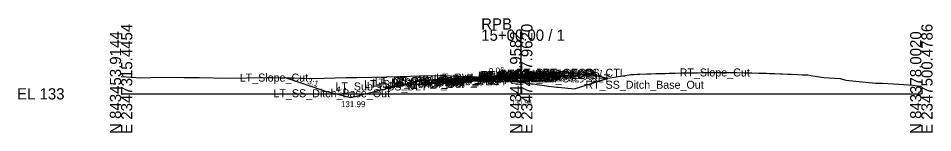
# Model space of a CAD drawing. Extents: x -76 to 2347760, y -10 to 844216.
# Drawn here: x -25.7 to 202.8, y -9.7 to 18.9 of the extents above; entities that cross this region are included whole.
import ezdxf

# ---------------------------------------------------------------- set-up
doc = ezdxf.new("R2010")
doc.units = 0
for name, color, linetype in [('Default', 7, 'Continuous'), ('Exist Cross Section Cell', 7, 'Continuous'), ('Exist XS Center Line Elevation Label', 7, 'Continuous'), ('Exist XS Ground Line', 7, 'Continuous'), ('Prop CMT Pvmt Course 1', 7, 'Continuous'), ('Prop CMT Pvmt Course 2', 7, 'Continuous'), ('Prop CMT Pvmt Course 3', 7, 'Continuous'), ('Prop CMT Pvmt Surface', 7, 'Continuous'), ('Prop CMT Pvmt Surface Shoulder', 7, 'Continuous'), ('Prop CMT Shld Paved Course 1', 7, 'Continuous'), ('Prop CMT Shld Paved Course 2', 7, 'Continuous'), ('Prop CMT Shld Paved Course 3', 7, 'Continuous'), ('Prop CMT Slope Grass', 7, 'Continuous'), ('Prop CMT Subgrade Earthwork', 7, 'Continuous'), ('Prop XS Ditch Standard Text', 7, 'Continuous'), ('Prop XS Earthwork Shape', 7, 'Continuous'), ('Prop XS SE Text', 7, 'Continuous'), ('Prop XS Side Slope Text', 7, 'Continuous'), ('Scratch_Level_0', 7, 'Continuous')]:
    doc.layers.add(name, color=color, linetype=linetype)

msp = doc.modelspace()

# ---------------------------------------------------------------- linework, layer by layer
at = {"layer": 'Exist Cross Section Cell'}
for p, q in [((100, 0), (100, 16.05)), ((0, 0), (100, 0)), ((100, 0), (200, 0))]:
    msp.add_line(p, q, dxfattribs=at)
at = {"layer": 'Exist XS Ground Line'}
msp.add_lwpolyline([(0, 4.33), (1.29, 4.27), (4.85, 4.03), (9.98, 4.14), (15.66, 4.12), (19.62, 4.12), (26.47, 3.9), (36.32, 4.12), (37.28, 4.11), (37.95, 4.11), (48.09, 3.87), (56.28, 4.11), (58.9, 4.11), (62.67, 4.2), (69.71, 4.3), (74.6, 4.51), (80.52, 4.57), (89.02, 4.24), (91.33, 4.06), (98.32, 3.17), (100, 2.93), (106.94, 1.94), (108.89, 1.64), (109.26, 1.63), (113.33, 1.28), (117.25, 2.5), (121.67, 3.89), (123.84, 4.22), (127.44, 4.85), (128.15, 4.83), (128.91, 4.89), (129.63, 4.92), (131.41, 4.98), (132.36, 5), (133.64, 5.04), (135.08, 5.08), (136.01, 5.11), (136.99, 5.14), (137.89, 5.15), (138.47, 5.17), (140.43, 5.21), (142.3, 5.24), (143.15, 5.26), (144.22, 5.28), (145.88, 5.31), (146.86, 5.33), (148.35, 5.35), (148.79, 5.34), (150.08, 5.34), (151.22, 5.33), (153.39, 5.31), (153.92, 5.3), (155.71, 5.27), (156.65, 5.26), (157.62, 5.24), (159.37, 5.2), (160, 5.19), (161.34, 5.15), (162.06, 5.12), (163.37, 5.07), (164.76, 5.02), (165.28, 5), (166.65, 4.94), (167.45, 4.91), (169.1, 4.83), (170.25, 4.76), (170.94, 4.71), (171.64, 4.71), (172.88, 4.51), (175.65, 4.07), (179.69, 3.85), (181.14, 3.4), (188.61, 2.7), (190.3, 2.68), (194.41, 2.4), (197.96, 2.17), (199.45, 1.96), (200, 1.88)], dxfattribs=at)
at = {"layer": 'Prop CMT Pvmt Course 1'}
for p, q in [((100, 4.79), (88, 4.07)), ((100, 4.79), (104, 5.03)), ((100, 4.54), (100, 4.79)), ((100, 4.54), (100, 4.79)), ((104, 4.78), (100, 4.54)), ((100, 4.54), (100, 4.67)), ((100, 4.67), (100, 4.67)), ((100, 4.67), (100, 4.54)), ((100, 4.54), (100, 4.67)), ((100, 4.67), (100, 4.67)), ((100, 4.67), (100, 4.54)), ((104, 5.03), (104, 4.78)), ((88, 3.82), (100, 4.54)), ((88, 4.07), (88, 3.82)), ((100, 4.54), (100, 4.54)), ((100, 4.54), (100, 4.54))]:
    msp.add_line(p, q, dxfattribs=at)
at = {"layer": 'Prop CMT Pvmt Course 2'}
for p, q in [((100, 4.54), (104, 4.78)), ((104, 4.78), (104, 4.45)), ((100, 4.54), (88, 3.82)), ((88, 3.49), (100, 4.21)), ((88, 3.82), (88, 3.49)), ((100, 4.21), (100, 4.54)), ((100, 4.21), (100, 4.54)), ((104, 4.45), (100, 4.21))]:
    msp.add_line(p, q, dxfattribs=at)
at = {"layer": 'Prop CMT Pvmt Course 3'}
for p, q in [((100, 4.21), (88, 3.49)), ((88, 3.16), (100, 3.88)), ((88, 3.49), (88, 3.16)), ((100, 4.21), (104, 4.45)), ((100, 3.88), (100, 4.21)), ((100, 3.88), (100, 4.21)), ((104, 4.12), (100, 3.88)), ((104, 4.45), (104, 4.12))]:
    msp.add_line(p, q, dxfattribs=at)
at = {"layer": 'Prop CMT Pvmt Surface'}
for q in [(88, 4.07), (104, 5.03)]:
    msp.add_line((100, 4.79), q, dxfattribs=at)
at = {"layer": 'Prop CMT Pvmt Surface Shoulder'}
for p, q in [((104, 5.03), (108, 5.27)), ((88, 4.07), (78, 3.47))]:
    msp.add_line(p, q, dxfattribs=at)
at = {"layer": 'Prop CMT Shld Paved Course 1'}
for p, q in [((104, 5.03), (108, 5.27)), ((108.24, 5.04), (104, 4.78)), ((104, 4.78), (104, 5.03)), ((108, 5.27), (108.24, 5.04)), ((77.73, 3.21), (88, 3.82)), ((78, 3.47), (77.73, 3.21)), ((88, 4.07), (78, 3.47)), ((88, 3.82), (88, 4.07))]:
    msp.add_line(p, q, dxfattribs=at)
at = {"layer": 'Prop CMT Shld Paved Course 2'}
for p, q in [((104, 4.78), (108.24, 5.04)), ((104, 4.45), (104, 4.78)), ((108.55, 4.72), (104, 4.45)), ((108.24, 5.04), (108.55, 4.72)), ((77.38, 2.85), (88, 3.49)), ((77.73, 3.21), (77.38, 2.85)), ((88, 3.82), (77.73, 3.21)), ((88, 3.49), (88, 3.82))]:
    msp.add_line(p, q, dxfattribs=at)
at = {"layer": 'Prop CMT Shld Paved Course 3'}
for p, q in [((104, 4.45), (108.55, 4.72)), ((108.55, 4.72), (109.05, 4.75)), ((109.05, 4.75), (109.36, 4.44)), ((76.52, 2.47), (88, 3.16)), ((76.88, 2.82), (76.52, 2.47)), ((77.38, 2.85), (76.88, 2.82)), ((88, 3.49), (77.38, 2.85)), ((88, 3.16), (88, 3.49)), ((104, 4.12), (104, 4.45)), ((109.36, 4.44), (104, 4.12))]:
    msp.add_line(p, q, dxfattribs=at)
at = {"layer": 'Prop CMT Slope Grass'}
for p, q in [((108, 5.27), (116, 5.27)), ((116, 5.27), (121.6, 3.87)), ((51.45, 0.49), (40.82, 4.04)), ((74.13, 3.16), (57.45, -1.01)), ((78, 3.47), (74.13, 3.16)), ((57.45, -1.01), (51.45, 0.49))]:
    msp.add_line(p, q, dxfattribs=at)
at = {"layer": 'Prop CMT Subgrade Earthwork'}
for p, q in [((104, 4.12), (117.41, 4.92)), ((76.52, 2.47), (69.71, 2.06)), ((88, 3.16), (76.52, 2.47)), ((100, 3.88), (88, 3.16)), ((100, 3.88), (104, 4.12))]:
    msp.add_line(p, q, dxfattribs=at)
at = {"layer": 'Prop XS Earthwork Shape'}
for points in [[(40.82, 4.04), (48.09, 3.87), (56.28, 4.11), (58.9, 4.11), (62.67, 4.2), (69.71, 4.3), (74.6, 4.51), (80.52, 4.57), (89.02, 4.24), (89.8, 4.18), (88, 4.07), (78, 3.47), (74.13, 3.16), (69.71, 2.06), (57.45, -1.01), (51.45, 0.49)], [(95.07, 3.58), (98.32, 3.17), (100, 2.93), (106.94, 1.94), (108.89, 1.64), (109.26, 1.63), (113.33, 1.28), (117.25, 2.5), (121.6, 3.87), (117.41, 4.92), (104, 4.12), (100, 3.88)], [(95.07, 3.58), (88, 3.16), (76.52, 2.47), (69.71, 2.06), (74.13, 3.16), (78, 3.47), (88, 4.07), (89.8, 4.18), (91.33, 4.06)]]:
    msp.add_lwpolyline(points, close=True, dxfattribs=at)

# ---------------------------------------------------------------- texts
at = {"layer": 'Default'}
msp.add_text('-', height=0.0001, dxfattribs=at).set_placement((0, 0))
at = {"layer": 'Exist Cross Section Cell'}
for s, p in [('RPB', (90, 16.05)), ('15+00.00 / 1', (90, 13.25)), ('EL 133', (-26, -1.4))]:
    msp.add_text(s, height=2.8, dxfattribs=at).set_placement(p)
for s, p in [('E 2347315.4454', (2.8, -10)), ('E 2347407.9620', (102.8, -10)), ('E 2347500.4786', (202.8, -10)), ('N 843453.9144', (0, -10)), ('N 843415.9582', (100, -10)), ('N 843378.0020', (200, -10))]:
    msp.add_text(s, height=2.8, rotation=90, dxfattribs=at).set_placement(p)
at = {"layer": 'Exist XS Center Line Elevation Label'}
msp.add_text('135.93', height=1.2, dxfattribs=at).set_placement((97.55, -2.67))
at = {"layer": 'Prop XS Ditch Standard Text'}
msp.add_text('131.99', height=1.5, dxfattribs=at).set_placement((54.93, -3.32))
at = {"layer": 'Prop XS SE Text'}
for s, rotation, p in [('0.06', 3.4336, (91.98, 4.93)), ('4:1', 14.0362, (64.2, 1.14))]:
    msp.add_text(s, height=1.5, rotation=rotation, dxfattribs=at).set_placement(p)
at = {"layer": 'Prop XS Side Slope Text'}
for s, rotation, p in [('4:1', 345.5351, (117.55, 5.06)), ('3:1', 341.5651, (46.43, 2.57)), ('4:1', 345.9638, (53.54, 0.53))]:
    msp.add_text(s, height=1.5, rotation=rotation, dxfattribs=at).set_placement(p)
at = {"layer": 'Scratch_Level_0'}
for s, p in [('LT_Slope_Cut', (29.64, 3.06)), ('LT_PV2_OEOT', (78.17, 2.82)), ('LT_PV1_OEOT', (78.74, 3.07)), ('RT_Sub_OEEOP', (89.17, 2.88)), ('LT_Sub_OEEOP', (89.21, 2.88)), ('RT_PV2_OEEOP', (89.26, 3.54)), ('RT_PV3_OEEOP', (89.26, 3.21)), ('LT_PV2_OEEOP', (89.31, 3.54)), ('LT_PV3_OEEOP', (89.31, 3.21)), ('RT_PV1_OEEOP', (89.83, 3.67)), ('LT_PV1_OEEOP', (89.87, 3.67)), ('RT_PV2_IEEOP', (89.91, 3.54)), ('LT_PV2_IEEOP', (89.95, 3.54)), ('RT_PV1_IEEOP', (90.47, 3.67)), ('LT_PV1_IEEOP', (90.52, 3.67)), ('RT_Sub_Trench_Out', (93.52, 3.44)), ('PV2_PGL', (93.91, 3.54)), ('RT_Sub_OEOT', (94.03, 3.12)), ('RT_PV2_OEOT', (94.13, 3.78)), ('RT_PV3_OEOT', (94.13, 3.45)), ('PV1_PGL', (94.47, 3.79)), ('RT_PV1_OEOT', (94.69, 4.03)), ('RT_PS3_Shelf_Out', (94.99, 3.75)), ('RT_PS2_OEOP', (98.42, 4.04)), ('RT_PS3_OEOP', (98.74, 3.72)), ('RT_Sub_OSS_DLT', (98.75, 2.85)), ('RT_PS1_OEOP', (98.76, 4.27)), ('RT_GS_OS_CTL', (105.32, 4.27)), ('RT_Slope_Cut', (139.59, 4.34)), ('LT_Sub_OSS_DLT', (53.56, 0.85)), ('LT_Sub_Trench_Out', (60.73, 1.47)), ('LT_PS3_Shelf_Out', (62.86, 1.82)), ('LT_GS_OS_CTL', (63.37, 2.15)), ('LT_PS3_OEOP', (67.62, 1.85)), ('LT_PS2_OEOP', (67.97, 2.21)), ('LT_PS1_OEOP', (68.8, 2.47)), ('LT_Sub_OEOT', (78.08, 2.16)), ('LT_PV3_OEOT', (78.17, 2.49)), ('RT_SS_Ditch_Base_Out', (116.03, 1.27)), ('LT_SS_Ditch_Base_Out', (38.08, -0.85))]:
    msp.add_text(s, height=2, dxfattribs=at).set_placement(p)

doc.saveas('drawing.dxf')
